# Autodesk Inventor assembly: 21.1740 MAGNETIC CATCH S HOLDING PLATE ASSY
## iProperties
Created: 2007-07
Part Number: 21.1740 MAGNETIC CATCH S HOLDING PLATE ASSY
Document SubType Name: Assembly
Designer: Andy Moles
Author: Andy Moles
